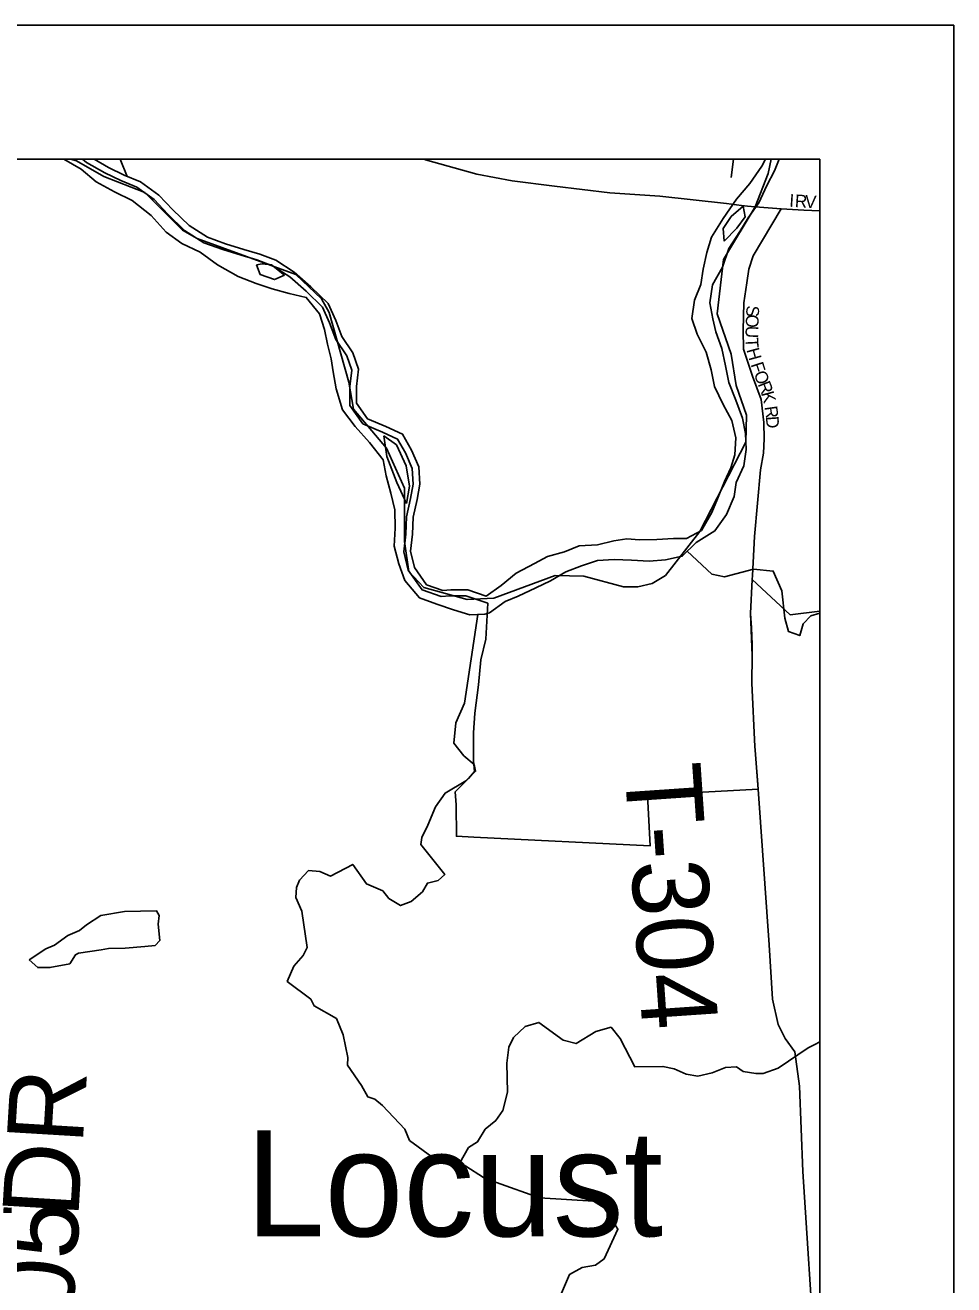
# Model space of a CAD drawing. Extents: x 0 to 40.4, y 0 to 22.
# Drawn here: x 8.807 to 9.5, y 20.061 to 21 of the extents above; entities that cross this region are included whole.
import ezdxf

# ---------------------------------------------------------------- set-up
doc = ezdxf.new("R2010")
doc.units = 0
for name, color, linetype in [('GM_X_City_Street', 7, 'Continuous'), ('GM_X_City_Street_Text', 7, 'Continuous'), ('GM_X_Corporation', 7, 'Continuous'), ('GM_X_County_Road_Text', 7, 'Continuous'), ('GM_X_Major_River', 7, 'Continuous'), ('GM_X_Minor_Lake', 7, 'Continuous'), ('GM_X_Minor_River', 7, 'Continuous'), ('GM_X_Township', 7, 'Continuous'), ('GM_X_Township_Road', 7, 'Continuous'), ('GM_X_Township_Road_Text', 7, 'Continuous'), ('GM_X_Unincorporated_Text', 7, 'Continuous'), ('SH_Data', 7, 'Continuous')]:
    doc.layers.add(name, color=color, linetype=linetype)

msp = doc.modelspace()

# ---------------------------------------------------------------- linework, layer by layer
at = {"layer": 'GM_X_City_Street'}
for points in [[(9.10502, 20.9), (9.10589, 20.89972), (9.14421, 20.88901), (9.17071, 20.88393), (9.20227, 20.87999), (9.24342, 20.87491), (9.28084, 20.87243), (9.33052, 20.86703), (9.34164, 20.86558)], [(9.33395, 20.88639), (9.33573, 20.9)], [(9.34164, 20.86558), (9.34613, 20.865), (9.35178, 20.8646), (9.37135, 20.8632)], [(9.34984, 20.58977), (9.35125, 20.61873), (9.35574, 20.66845), (9.35802, 20.68083), (9.35852, 20.69169), (9.35827, 20.70382), (9.35619, 20.72084), (9.34976, 20.73827), (9.34312, 20.7584), (9.34291, 20.77251), (9.34333, 20.79306), (9.34568, 20.80801), (9.34703, 20.81815), (9.35041, 20.82806), (9.37135, 20.8632)], [(9.37135, 20.8632), (9.38809, 20.8622), (9.4, 20.86167)]]:
    msp.add_lwpolyline(points, dxfattribs=at)
at = {"layer": 'GM_X_Corporation'}
for points in [[(9.4, 20.56303), (9.4, 20.9), (8.85008, 20.9)], [(8.85008, 20.9), (8.85322, 20.89771), (8.86679, 20.88992), (8.87877, 20.8841), (8.89055, 20.87929), (8.90347, 20.86993), (8.91384, 20.85914), (8.92629, 20.84703), (8.94066, 20.83782), (8.95483, 20.83267), (8.96859, 20.82844), (8.98021, 20.82505), (8.99177, 20.82069), (9.00475, 20.81236), (9.01692, 20.80164), (9.02913, 20.78973), (9.03441, 20.77807), (9.03905, 20.76559), (9.04733, 20.75351), (9.05098, 20.74281), (9.04952, 20.73064), (9.04948, 20.71656), (9.05925, 20.70274), (9.07392, 20.6966), (9.08515, 20.69148), (9.09114, 20.6811), (9.09604, 20.66949), (9.0967, 20.6578), (9.09487, 20.64702), (9.09175, 20.6335), (9.09127, 20.62049), (9.08972, 20.60731), (9.09309, 20.59369), (9.10338, 20.57905), (9.11756, 20.57415), (9.12432, 20.57456), (9.13602, 20.57454), (9.15245, 20.56903), (9.15106, 20.54213), (9.14731, 20.52686), (9.14541, 20.50821), (9.14287, 20.48696), (9.14165, 20.47243), (9.14172, 20.45159), (9.14259, 20.4435), (9.13792, 20.43828), (9.12818, 20.42847), (9.12873, 20.41864), (9.12904, 20.39527), (9.14209, 20.39462), (9.27343, 20.38813), (9.27143, 20.42596), (9.35401, 20.43029), (9.35237, 20.45302), (9.35191, 20.45941), (9.3517, 20.4623), (9.34923, 20.50955), (9.34956, 20.53003), (9.34846, 20.56135), (9.34969, 20.58665), (9.37804, 20.5605), (9.4, 20.56303)]]:
    msp.add_lwpolyline(points, dxfattribs=at)
at = {"layer": 'GM_X_Major_River'}
for points in [[(8.83616, 20.9), (8.84902, 20.89278), (8.86037, 20.88329), (8.874, 20.87569), (8.88725, 20.86923), (8.90124, 20.85822), (8.91258, 20.8457), (8.92431, 20.83734), (8.93794, 20.83088), (8.9508, 20.82138), (8.96632, 20.81264), (8.97958, 20.80732), (8.99169, 20.8035), (9.00419, 20.80007), (9.01707, 20.79702), (9.0269, 20.78488), (9.03066, 20.77313), (9.03291, 20.76214), (9.03553, 20.75115), (9.03703, 20.74168), (9.03927, 20.72879), (9.04416, 20.71325), (9.05361, 20.70073), (9.06419, 20.68897), (9.07439, 20.67607), (9.07664, 20.66395), (9.08002, 20.65106), (9.08302, 20.63856), (9.08336, 20.62492), (9.08258, 20.61166), (9.08596, 20.59839), (9.09047, 20.58589), (9.10144, 20.57299), (9.11431, 20.56842), (9.12681, 20.56423), (9.13893, 20.56042), (9.1503, 20.56078)], [(9.11888, 20.57864), (9.10676, 20.58283), (9.0977, 20.59572), (9.0947, 20.60785), (9.09618, 20.62045), (9.09665, 20.63323), (9.09971, 20.64648), (9.10164, 20.65784), (9.10091, 20.67072), (9.09563, 20.68323), (9.08884, 20.69499), (9.07635, 20.70069), (9.06272, 20.7064), (9.05441, 20.71816), (9.05444, 20.73066), (9.05598, 20.74354), (9.05184, 20.75567), (9.04353, 20.7678), (9.03901, 20.77993), (9.03336, 20.79244), (9.0205, 20.80497), (9.00802, 20.81598), (8.9944, 20.82471), (8.98228, 20.82928), (8.97054, 20.83271), (8.95691, 20.8369), (8.94327, 20.84185), (8.92965, 20.85059), (8.91755, 20.86236), (8.90696, 20.87336), (8.89334, 20.88323), (8.88123, 20.88818), (8.86949, 20.89388), (8.85883, 20.9)], [(9.35945, 20.9), (9.35689, 20.89491), (9.34776, 20.88205), (9.33788, 20.87032), (9.32799, 20.85594), (9.31924, 20.84194), (9.31581, 20.83058), (9.31312, 20.81809), (9.3112, 20.80673), (9.30662, 20.79499), (9.3047, 20.78136), (9.30846, 20.76961), (9.31525, 20.75634), (9.31901, 20.74307), (9.32163, 20.73057), (9.32804, 20.71729), (9.33446, 20.70516), (9.33746, 20.69228), (9.33667, 20.67978), (9.33361, 20.66993), (9.32904, 20.65971), (9.32371, 20.64684), (9.31951, 20.63662), (9.3119, 20.62338), (9.30052, 20.61733), (9.29104, 20.61735), (9.27853, 20.61662), (9.26565, 20.61626), (9.25617, 20.61703), (9.24632, 20.61554), (9.23418, 20.61253), (9.22053, 20.61179), (9.20953, 20.60727), (9.19702, 20.60388), (9.18715, 20.59859), (9.17349, 20.59142), (9.16248, 20.58235), (9.15109, 20.57442), (9.13745, 20.57898), (9.12495, 20.57901), (9.11888, 20.57864)], [(9.1503, 20.56078), (9.15371, 20.56191), (9.16548, 20.57022), (9.17497, 20.57437), (9.18824, 20.58041), (9.19925, 20.58569), (9.21063, 20.59249), (9.22239, 20.59702), (9.23415, 20.60078), (9.24666, 20.60152), (9.25955, 20.60112), (9.27281, 20.60034), (9.28494, 20.60145), (9.29745, 20.60408), (9.30771, 20.61429), (9.32176, 20.62298), (9.3305, 20.63509), (9.33622, 20.64871), (9.33776, 20.65894), (9.34347, 20.67143), (9.34502, 20.68355), (9.34467, 20.69567), (9.34242, 20.70704), (9.33753, 20.72031), (9.33225, 20.73358), (9.32963, 20.74608), (9.32701, 20.75897), (9.32249, 20.77148), (9.32024, 20.78095), (9.31799, 20.79308), (9.31992, 20.80633), (9.32753, 20.81958), (9.33211, 20.83359), (9.34048, 20.84607), (9.34657, 20.85629), (9.35455, 20.86764), (9.36065, 20.88051), (9.36636, 20.89148), (9.36968, 20.9)], [(9.3428, 20.86501), (9.33406, 20.85745), (9.32797, 20.84837), (9.32871, 20.83889)], [(9.32871, 20.83889), (9.33821, 20.84873), (9.34429, 20.85705), (9.3428, 20.86501)], [(9.00081, 20.81372), (8.99098, 20.82131), (8.98416, 20.82208), (8.97999, 20.82133)], [(8.97999, 20.82133), (8.98262, 20.81413), (8.99323, 20.81032), (9.00081, 20.81372)], [(9.07481, 20.69388), (9.07705, 20.67834), (9.08458, 20.65901), (9.09175, 20.64346)], [(9.09175, 20.64346), (9.09405, 20.65634), (9.09144, 20.6715), (9.08427, 20.68704), (9.07481, 20.69388)]]:
    msp.add_lwpolyline(points, dxfattribs=at)
at = {"layer": 'GM_X_Minor_Lake'}
for points in [[(8.90659, 20.32975), (8.90734, 20.3362), (8.90544, 20.33961), (8.88157, 20.3392), (8.86376, 20.33614), (8.85315, 20.3293), (8.84785, 20.32513), (8.83913, 20.32132), (8.82929, 20.31411), (8.82285, 20.31145), (8.81035, 20.30309)], [(8.81035, 20.30309), (8.8168, 20.29742), (8.82589, 20.29743), (8.84067, 20.3001), (8.84483, 20.30693), (8.84711, 20.30807), (8.86416, 20.31074), (8.86946, 20.31151), (8.88197, 20.3119), (8.89675, 20.31306), (8.90433, 20.31383), (8.90774, 20.31762), (8.90659, 20.32975)]]:
    msp.add_lwpolyline(points, dxfattribs=at)
at = {"layer": 'GM_X_Minor_River'}
for points in [[(8.88349, 20.88726), (8.87814, 20.9)], [(9.30119, 20.60781), (9.31943, 20.59071), (9.32891, 20.58882), (9.35051, 20.59454), (9.36529, 20.59304), (9.37175, 20.57827), (9.37404, 20.5578), (9.3767, 20.54795), (9.38504, 20.54492), (9.38769, 20.55364), (9.39337, 20.55972), (9.4, 20.56156)], [(9.2074, 20.05454), (9.21345, 20.06858), (9.22292, 20.0739), (9.23277, 20.07543), (9.23921, 20.08036), (9.24942, 20.10236), (9.23917, 20.11827), (9.23121, 20.12319), (9.19103, 20.12579), (9.15881, 20.13712), (9.15274, 20.13863), (9.13264, 20.15149), (9.11065, 20.15639), (9.09397, 20.1685), (9.09055, 20.17684), (9.07385, 20.19463), (9.06816, 20.19917), (9.06286, 20.20106), (9.0583, 20.2094), (9.04768, 20.22455), (9.04805, 20.23023), (9.04462, 20.24729), (9.03968, 20.25941), (9.023, 20.26887), (9.02034, 20.27379), (9.00289, 20.28704), (9.00781, 20.29841), (9.01462, 20.30638), (9.01765, 20.31245), (9.01383, 20.33936), (9.00927, 20.34959), (9.00965, 20.35718), (9.01192, 20.36249), (9.01873, 20.3697), (9.02707, 20.36895), (9.03503, 20.36555), (9.0517, 20.37429), (9.06194, 20.35989), (9.07408, 20.35461), (9.07863, 20.34892), (9.08735, 20.34363), (9.09531, 20.34667), (9.10364, 20.35388), (9.10742, 20.36033), (9.11538, 20.36224), (9.1203, 20.36679), (9.10247, 20.38914), (9.10322, 20.39445), (9.10776, 20.40355), (9.11343, 20.4172), (9.12062, 20.42745), (9.13615, 20.43657), (9.14335, 20.44378), (9.1422, 20.4487), (9.13462, 20.45514), (9.12703, 20.46461), (9.12853, 20.47977), (9.13496, 20.49456), (9.14495, 20.56061)], [(9.13159, 20.15172), (9.13794, 20.16325), (9.14475, 20.16743), (9.15043, 20.17691), (9.15838, 20.18337), (9.16368, 20.19096), (9.16708, 20.20461), (9.16668, 20.22621), (9.16818, 20.23797), (9.17159, 20.24518), (9.18029, 20.25353), (9.19052, 20.25657), (9.20873, 20.24333), (9.21821, 20.24069), (9.23298, 20.2498), (9.24434, 20.25285), (9.25117, 20.24452), (9.26219, 20.22331), (9.28303, 20.22371), (9.29137, 20.22183), (9.30047, 20.21805), (9.30919, 20.21654), (9.3198, 20.21883), (9.32965, 20.22301), (9.33798, 20.2234), (9.34291, 20.22), (9.35239, 20.2185), (9.3577, 20.2185), (9.36906, 20.22231), (9.39141, 20.2375), (9.39633, 20.24016), (9.4, 20.24195)]]:
    msp.add_lwpolyline(points, dxfattribs=at)
at = {"layer": 'GM_X_Township'}
for p, q in [((8.84124, 20.9), (8.84124, 20.9)), ((9.36385, 20.9), (9.36385, 20.9))]:
    msp.add_line(p, q, dxfattribs=at)
msp.add_lwpolyline([(8.84124, 20.9), (8.84557, 20.89889), (8.86602, 20.88729), (8.89673, 20.87521), (8.92462, 20.84719), (8.9356, 20.841), (9.00917, 20.81406), (9.02841, 20.79601), (9.03402, 20.78569), (9.04876, 20.73385), (9.05237, 20.71367), (9.07683, 20.68454), (9.09025, 20.65476), (9.09033, 20.61507), (9.09358, 20.5926), (9.10481, 20.58066), (9.13704, 20.57182), (9.15684, 20.57277), (9.20266, 20.58982), (9.22397, 20.58923), (9.25358, 20.58134), (9.26423, 20.58124), (9.27491, 20.5838), (9.28486, 20.58978), (9.31066, 20.62261), (9.34478, 20.68918), (9.34535, 20.70933), (9.33757, 20.73145), (9.33398, 20.75467), (9.32361, 20.7848), (9.32818, 20.82543), (9.35178, 20.86459), (9.3615, 20.88935), (9.36385, 20.9)], dxfattribs=at)
at = {"layer": 'GM_X_Township_Road'}
for points in [[(9.34903, 20.5508), (9.34846, 20.56135), (9.34969, 20.58665), (9.34984, 20.58977)], [(9.35374, 20.43393), (9.35237, 20.45302), (9.35191, 20.45941), (9.3517, 20.4623), (9.34923, 20.50955), (9.34956, 20.53003), (9.3497, 20.53819), (9.34903, 20.5508)], [(9.4, 19.98306), (9.39659, 20.00368), (9.38747, 20.14537), (9.38495, 20.20897), (9.38148, 20.23448), (9.37424, 20.24455), (9.36896, 20.25488), (9.36468, 20.27394), (9.36235, 20.3144), (9.35401, 20.43029), (9.35374, 20.43393)]]:
    msp.add_lwpolyline(points, dxfattribs=at)
at = {"layer": 'SH_Data'}
for p, q in [((2.5, 21), (9.5, 21)), ((9.5, 21), (9.5, 14)), ((2.6, 20.9), (9.4, 20.9)), ((9.4, 20.9), (9.4, 14.1))]:
    msp.add_line(p, q, dxfattribs=at)

# ---------------------------------------------------------------- texts
at = {"layer": 'GM_X_City_Street_Text'}
for s, rotation, p in [('I', 356.3255, (9.37708, 20.86469)), ('R', 356.34305, (9.38124, 20.86442)), ('V', 356.3255, (9.38873, 20.86394)), ('O', 267.56084, (9.34513, 20.78449)), ('S', 267.56741, (9.34542, 20.79115)), ('U', 268.78789, (9.34477, 20.77594)), ('T', 272.94164, (9.34461, 20.76686)), ('H', 285.18729, (9.3453, 20.75803)), ('F', 288.04508, (9.3484, 20.74711)), ('O', 290.54446, (9.35062, 20.74035)), ('R', 291.38144, (9.3536, 20.7324)), ('K', 285.12287, (9.35624, 20.72568)), ('R', 278.06486, (9.35874, 20.71547)), ('D', 274.28807, (9.35977, 20.7082))]:
    msp.add_text(s, height=0.00947, rotation=rotation, dxfattribs=at).set_placement(p)
at = {"layer": 'GM_X_County_Road_Text'}
for s, rotation, p in [('DR', 86.54661, (8.84695, 20.11036)), ('C-305', 86.18598, (8.83463, 19.91468))]:
    msp.add_text(s, height=0.056818, rotation=rotation, dxfattribs=at).set_placement(p)
at = {"layer": 'GM_X_Township_Road_Text'}
msp.add_text('T-304', height=0.056818, rotation=273.91414, dxfattribs=at).set_placement((9.25428, 20.44784))
at = {"layer": 'GM_X_Unincorporated_Text'}
msp.add_text('Locust', height=0.078977, rotation=0.00001, dxfattribs=at).set_placement((8.97197, 20.09703))

doc.saveas('drawing.dxf')
